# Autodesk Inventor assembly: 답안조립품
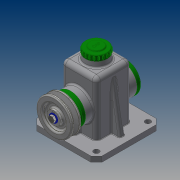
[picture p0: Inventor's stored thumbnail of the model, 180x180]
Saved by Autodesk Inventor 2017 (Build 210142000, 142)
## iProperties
Part Number: 답안조립품
Material: 일반
Document SubType Name: Assembly
Designer: 20
Author: 20
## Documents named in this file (14)
- C:\Users\20\Desktop\470818V1008\답안조립품.iam
- C:\Users\20\Desktop\470818V1008\본체.ipt
- C:\Users\20\Desktop\470818V1008\앞커버.ipt
- C:\Users\20\Desktop\470818V1008\뒤커버.ipt
- C:\Users\20\Desktop\470818V1008\상부캡.ipt
- C:\Users\20\Desktop\470818V1008\베어링 15 x 35 x 11.ipt
- C:\Users\20\Desktop\470818V1008\오일실 15 25 7.ipt
- C:\Users\20\Desktop\470818V1008\멈춤링 15 x 1.ipt
- C:\Users\20\Desktop\470818V1008\축.ipt
- C:\Users\20\Desktop\470818V1008\키 5 x 5 x 14.ipt
- C:\Users\20\Desktop\470818V1008\V-벨트풀리.ipt
- C:\Users\20\Desktop\470818V1008\와셔.ipt
- C:\Users\20\Desktop\470818V1008\볼트 M6 x 12.ipt
- C:\Users\20\Desktop\470818V1008\볼트 M4 x 10.ipt
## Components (1 placed, 1 different names)
1. V-벨트풀리:1
